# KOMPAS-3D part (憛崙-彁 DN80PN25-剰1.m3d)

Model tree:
1. Объединить компоненты:1  (labels: СЕНС-ПР DN80PN25-ДП1)

Referenced files in D:\Савин\!СЕНСОР\3D для заказчика\!Новый перечень\СЕНС-ПР\3. СЕНС-ПР-ДП\DN80\: СЕНС-ПР DN80PN25-ДП1.a3d
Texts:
  СЕНС-ПР DN80PN25-ДП1
  ООО НПП Сенсор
